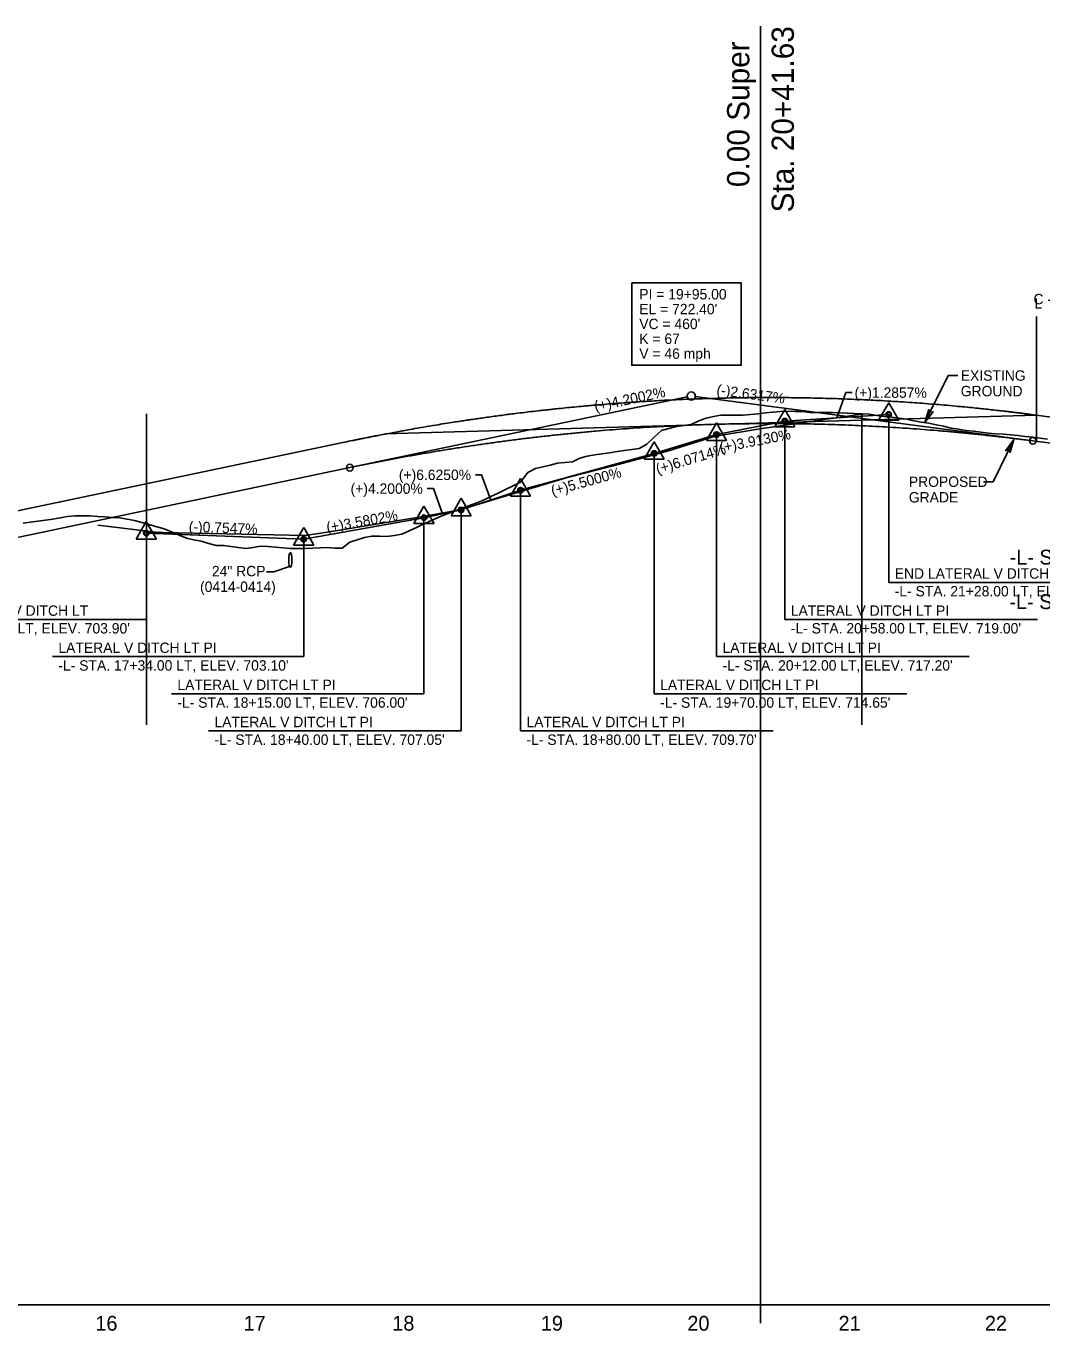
# Model space of a CAD drawing. Extents: x 1518255 to 1527303, y 471773 to 504546.
# Drawn here: x 1520117 to 1520802, y 501127 to 502006 of the extents above; entities that cross this region are included whole.
import ezdxf

# ---------------------------------------------------------------- set-up
doc = ezdxf.new("R2010")
doc.units = 0
for name, color, linetype in [('Exist Profile Cell', 7, 'Continuous'), ('Exist Vertical Profile Ground Line', 7, 'Continuous'), ('Exist Vertical Profile Horizontal Axis Label Major', 7, 'Continuous'), ('Prop Dimension', 7, 'Continuous'), ('Prop Grid Mask', 7, 'Continuous'), ('Prop PFL Cross Pipe CELL', 7, 'Continuous'), ('Prop PFL Cross Pipe Text CELL', 7, 'Continuous'), ('Prop PFL Ditch Label CELL', 7, 'Continuous'), ('Prop Terminator CELL', 7, 'Continuous'), ('Prop Vertical Profile Curve Label', 7, 'Continuous'), ('Prop Vertical Profile Grade', 7, 'Continuous'), ('Prop Vertical Profile Grade Label', 7, 'Continuous'), ('Prop VPI Label', 7, 'Continuous'), ('Scratch_Level_2', 7, 'Continuous'), ('Scratch_Level_3', 7, 'Continuous'), ('Scratch_Level_7', 7, 'Continuous'), ('Scratch_Level_9', 7, 'Continuous')]:
    doc.layers.add(name, color=color, linetype=linetype)

msp = doc.modelspace()

# ---------------------------------------------------------------- linework, layer by layer
at = {"layer": 'Exist Profile Cell'}
msp.add_line((1519570.42, 501145.02), (1521170.42, 501145.02), dxfattribs=at)
at = {"layer": 'Exist Vertical Profile Ground Line'}
for points in [[(1520115.42, 501671.34), (1520120.42, 501672.01), (1520125.42, 501672.69), (1520130.42, 501673.38), (1520135.42, 501674.07), (1520140.42, 501674.84), (1520145.42, 501675.74), (1520150.42, 501676.26), (1520155.42, 501676.35), (1520160.42, 501676.16), (1520165.42, 501675.84), (1520170.42, 501675.53), (1520175.42, 501675.22), (1520180.42, 501674.88), (1520185.42, 501674.02), (1520190.42, 501673.16), (1520195.42, 501671.75), (1520200.42, 501670.34), (1520205.42, 501668.92), (1520210.42, 501667.51), (1520215.42, 501665.45), (1520220.42, 501663.34), (1520225.42, 501661.22), (1520230.42, 501660.13), (1520235.42, 501659.3), (1520240.42, 501657.63), (1520245.42, 501656.2), (1520250.42, 501656.32), (1520255.42, 501655.73), (1520260.42, 501654.98), (1520265.42, 501654.31), (1520270.42, 501655.03), (1520275.42, 501655.83), (1520280.42, 501655.67), (1520285.42, 501655.2), (1520290.42, 501654.73), (1520295.42, 501654.27), (1520300.42, 501654.19), (1520305.42, 501654.36), (1520310.42, 501654.51), (1520315.42, 501654.68), (1520320.42, 501654.96), (1520325.42, 501654.48), (1520330.42, 501654.44), (1520335.42, 501658.63), (1520340.42, 501660.21), (1520345.42, 501661.65), (1520350.42, 501662.58), (1520355.42, 501662.49), (1520360.42, 501662.36), (1520365.42, 501662.98), (1520370.42, 501664.03), (1520375.42, 501666.1), (1520380.42, 501668.5), (1520385.42, 501670.89), (1520390.42, 501673.21), (1520395.42, 501675.39), (1520400.42, 501677.34), (1520405.42, 501679.22), (1520410.42, 501681.11), (1520415.42, 501683), (1520420.42, 501684.89), (1520425.42, 501686.9), (1520430.42, 501689.21), (1520435.42, 501691.57), (1520440.42, 501693.97), (1520445.42, 501696.52), (1520450.42, 501699.04), (1520455.42, 501705.39), (1520460.42, 501708.1), (1520465.42, 501709.26), (1520470.42, 501710.48), (1520475.42, 501711.7), (1520480.42, 501712.22), (1520485.42, 501712.72), (1520490.42, 501715.01), (1520495.42, 501716.42), (1520500.42, 501717.25), (1520505.42, 501718.07), (1520510.42, 501718.79), (1520515.42, 501719.51), (1520520.42, 501720.2), (1520525.42, 501720.9), (1520530.42, 501721.6), (1520535.42, 501724.63), (1520540.42, 501729.18), (1520545.42, 501733.69), (1520550.42, 501734.98), (1520555.42, 501736.34), (1520560.42, 501737.04), (1520565.42, 501737.73), (1520570.42, 501740.35)], [(1520570.42, 501740.35), (1520575.42, 501742.01), (1520580.42, 501743.27), (1520585.42, 501744.04), (1520590.42, 501744.07), (1520595.42, 501744.11), (1520600.42, 501744.14), (1520605.42, 501744.52), (1520610.42, 501745.02), (1520615.42, 501745.53), (1520620.42, 501746), (1520625.42, 501746.44), (1520630.42, 501746.68), (1520635.42, 501746.59), (1520640.42, 501746.45), (1520645.42, 501745.97), (1520650.42, 501745.92), (1520655.42, 501745.86), (1520660.42, 501745.77), (1520665.42, 501745.57), (1520670.42, 501745.37), (1520675.42, 501745.13), (1520680.42, 501744.95), (1520685.42, 501744.79), (1520690.42, 501743.89), (1520695.42, 501743.27), (1520700.42, 501742.7), (1520705.42, 501742.14), (1520710.42, 501741.27), (1520715.42, 501740.26), (1520720.42, 501739.4), (1520725.42, 501738.6), (1520730.42, 501737.62), (1520735.42, 501736.56), (1520740.42, 501735.41), (1520745.42, 501734.57), (1520750.42, 501733.82), (1520755.42, 501733.22), (1520760.42, 501732.61), (1520765.42, 501732.02), (1520770.42, 501731.59), (1520775.42, 501731.16), (1520780.42, 501730.74), (1520785.42, 501730.3), (1520790.42, 501729.78), (1520795.42, 501729.18), (1520800.42, 501728.53), (1520805.42, 501727.89)]]:
    msp.add_lwpolyline(points, dxfattribs=at)
at = {"layer": 'Prop Dimension'}
for p, q in [((1520738.55, 501770.75), (1520722.8, 501739.02)), ((1520744.94, 501770.75), (1520738.55, 501770.75)), ((1520768.65, 501699.24), (1520782.71, 501727.57)), ((1520762.26, 501699.24), (1520768.65, 501699.24))]:
    msp.add_line(p, q, dxfattribs=at)
at = {"layer": 'Prop Grid Mask'}
msp.add_lwpolyline([(1520525.4, 501833.18), (1520598.93, 501833.18), (1520598.93, 501777.64), (1520525.4, 501777.64)], close=True, dxfattribs=at)
at = {"layer": 'Prop PFL Cross Pipe CELL'}
msp.add_ellipse((1520295.42, 501646.47), major_axis=(0, -5), ratio=0.2, dxfattribs=at)
at = {"layer": 'Prop PFL Cross Pipe Text CELL'}
for p, q in [((1520279.32, 501638.53), (1520284.25, 501638.53)), ((1520284.25, 501638.53), (1520294.91, 501642.16))]:
    msp.add_line(p, q, dxfattribs=at)
at = {"layer": 'Prop PFL Ditch Label CELL'}
for p, q in [((1520663.42, 501742.27), (1520669.61, 501759.26)), ((1520669.61, 501759.26), (1520673.7, 501759.26)), ((1520698.41, 501752.37), (1520691.64, 501740.61)), ((1520698.41, 501752.37), (1520705.23, 501740.61)), ((1520582.42, 501731.02), (1520628.42, 501740.02)), ((1520628.41, 501747.87), (1520621.64, 501736.11)), ((1520628.41, 501747.87), (1520635.23, 501736.11)), ((1520628.42, 501740.02), (1520698.42, 501744.52)), ((1520628.42, 501740.02), (1520628.42, 501606.48)), ((1520691.64, 501740.61), (1520705.23, 501740.61)), ((1520698.42, 501744.52), (1520698.42, 501631.48)), ((1520540.42, 501718.27), (1520582.42, 501731.02)), ((1520582.41, 501738.87), (1520575.64, 501727.11)), ((1520582.41, 501738.87), (1520589.23, 501727.11)), ((1520582.42, 501731.02), (1520582.42, 501581.48)), ((1520621.64, 501736.11), (1520635.23, 501736.11)), ((1520540.41, 501726.12), (1520533.64, 501714.36)), ((1520540.41, 501726.12), (1520547.23, 501714.36)), ((1520575.64, 501727.11), (1520589.23, 501727.11)), ((1520450.42, 501693.52), (1520540.42, 501718.27)), ((1520533.64, 501714.36), (1520547.23, 501714.36)), ((1520540.42, 501718.27), (1520540.42, 501556.48)), ((1520424.22, 501703.88), (1520420.13, 501703.88)), ((1520430.42, 501686.89), (1520424.22, 501703.88)), ((1520450.41, 501701.37), (1520443.64, 501689.61)), ((1520450.41, 501701.37), (1520457.23, 501689.61)), ((1520391.72, 501694.63), (1520387.63, 501694.63)), ((1520397.92, 501677.64), (1520391.72, 501694.63)), ((1520410.41, 501688.12), (1520403.64, 501676.36)), ((1520410.41, 501688.12), (1520417.23, 501676.36)), ((1520410.42, 501680.27), (1520450.42, 501693.52)), ((1520443.64, 501689.61), (1520457.23, 501689.61)), ((1520450.42, 501693.52), (1520450.42, 501531.48)), ((1520385.41, 501682.87), (1520378.64, 501671.11)), ((1520385.41, 501682.87), (1520392.23, 501671.11)), ((1520385.42, 501675.02), (1520410.42, 501680.27)), ((1520410.42, 501680.27), (1520410.42, 501531.48)), ((1520198.41, 501672.37), (1520191.64, 501660.61)), ((1520198.41, 501672.37), (1520205.23, 501660.61)), ((1520304.42, 501660.52), (1520385.42, 501675.02)), ((1520378.64, 501671.11), (1520392.23, 501671.11)), ((1520385.42, 501675.02), (1520385.42, 501556.48)), ((1520403.64, 501676.36), (1520417.23, 501676.36)), ((1520191.64, 501660.61), (1520205.23, 501660.61)), ((1520198.42, 501664.52), (1520304.42, 501660.52)), ((1520198.42, 501664.52), (1520198.42, 501606.48)), ((1520304.41, 501668.37), (1520297.64, 501656.61)), ((1520304.41, 501668.37), (1520311.23, 501656.61)), ((1520304.42, 501660.52), (1520304.42, 501581.48)), ((1520297.64, 501656.61), (1520311.23, 501656.61)), ((1520698.42, 501631.48), (1520868.57, 501631.48)), ((1520028.27, 501606.48), (1520198.42, 501606.48)), ((1520628.42, 501606.48), (1520798.57, 501606.48)), ((1520135.13, 501581.48), (1520304.42, 501581.48)), ((1520582.42, 501581.48), (1520752.57, 501581.48)), ((1520215.27, 501556.48), (1520385.42, 501556.48)), ((1520540.42, 501556.48), (1520710.57, 501556.48)), ((1520240.27, 501531.48), (1520410.42, 501531.48)), ((1520450.42, 501531.48), (1520620.57, 501531.48))]:
    msp.add_line(p, q, dxfattribs=at)
for centre, radius in [((1520628.42, 501740.02), 1.84), ((1520628.42, 501740.02), 1.26), ((1520698.42, 501744.52), 1.84), ((1520698.42, 501744.52), 1.26), ((1520582.42, 501731.02), 1.84), ((1520582.42, 501731.02), 1.26), ((1520540.42, 501718.27), 1.84), ((1520540.42, 501718.27), 1.26), ((1520450.42, 501693.52), 1.84), ((1520450.42, 501693.52), 1.26), ((1520410.42, 501680.27), 1.84), ((1520410.42, 501680.27), 1.26), ((1520385.42, 501675.02), 1.84), ((1520385.42, 501675.02), 1.26), ((1520198.42, 501664.52), 1.84), ((1520198.42, 501664.52), 1.26), ((1520304.42, 501660.52), 1.84), ((1520304.42, 501660.52), 1.26)]:
    msp.add_circle(centre, radius, dxfattribs=at)
at = {"layer": 'Prop Terminator CELL'}
for points in [[(1520725.41, 501747.77), (1520722.8, 501739.02), (1520728.25, 501746.41), (1520726.31, 501746.1)], [(1520780.1, 501718.82), (1520782.71, 501727.57), (1520777.26, 501720.18), (1520779.2, 501720.5)]]:
    msp.add_lwpolyline(points, close=True, dxfattribs=at)
at = {"layer": 'Prop Vertical Profile Curve Label'}
msp.add_line((1520797.9, 501726.42), (1520797.9, 501810.55), dxfattribs=at)
for centre in [(1520795.42, 501726.75), (1520335.42, 501708.71)]:
    msp.add_circle(centre, 2.25, dxfattribs=at)
at = {"layer": 'Prop Vertical Profile Grade'}
for p, q in [((1520795.42, 501726.75), (1520830.42, 501722.14)), ((1519930.42, 501623.66), (1520335.42, 501708.71))]:
    msp.add_line(p, q, dxfattribs=at)
msp.add_spline([(1520335.42, 501708.71), (1520344.62, 501710.61), (1520353.82, 501712.45), (1520363.02, 501714.23), (1520372.22, 501715.94), (1520381.42, 501717.59), (1520390.62, 501719.17), (1520399.82, 501720.7), (1520409.02, 501722.16), (1520418.22, 501723.56), (1520427.42, 501724.89), (1520436.62, 501726.16), (1520445.82, 501727.37), (1520455.02, 501728.52), (1520464.22, 501729.6), (1520473.42, 501730.62), (1520482.62, 501731.58), (1520491.82, 501732.48), (1520501.02, 501733.31), (1520510.22, 501734.08), (1520519.42, 501734.78), (1520528.62, 501735.43), (1520537.82, 501736.01), (1520547.02, 501736.53), (1520556.22, 501736.98), (1520565.42, 501737.37), (1520574.62, 501737.7), (1520583.82, 501737.97), (1520593.02, 501738.17), (1520602.22, 501738.31), (1520611.42, 501738.39), (1520620.62, 501738.41), (1520629.82, 501738.36), (1520639.02, 501738.25), (1520648.22, 501738.07), (1520657.42, 501737.84), (1520666.62, 501737.54), (1520675.82, 501737.18), (1520685.02, 501736.75), (1520694.22, 501736.26), (1520703.42, 501735.71), (1520712.62, 501735.1), (1520721.82, 501734.42), (1520731.02, 501733.68), (1520740.22, 501732.88), (1520749.42, 501732.02), (1520758.62, 501731.09), (1520767.82, 501730.1), (1520777.02, 501729.05), (1520786.22, 501727.93), (1520795.42, 501726.75)], degree=3, dxfattribs=at)
at = {"layer": 'Prop VPI Label'}
for p, q in [((1520335.42, 501708.71), (1520562.72, 501756.45)), ((1520795.42, 501726.75), (1520568.14, 501756.66))]:
    msp.add_line(p, q, dxfattribs=at)
msp.add_circle((1520565.42, 501757.02), 2.75, dxfattribs=at)
at = {"layer": 'Scratch_Level_3'}
for p, q in [((1520198.42, 501745.02), (1520198.42, 501535.6)), ((1520613.26, 501735.02), (1520647.31, 501740.02)), ((1520647.31, 501740.02), (1520681.54, 501745.02)), ((1520680.42, 501745.02), (1520680.42, 501535.6)), ((1520581.57, 501730.02), (1520613.26, 501735.02)), ((1520550, 501720.02), (1520565.74, 501725.02)), ((1520565.74, 501725.02), (1520581.57, 501730.02)), ((1520512.83, 501710.02), (1520532.14, 501715.02)), ((1520532.14, 501715.02), (1520550, 501720.02)), ((1520474.16, 501700.02), (1520493.44, 501705.02)), ((1520493.44, 501705.02), (1520512.83, 501710.02)), ((1520408.71, 501680.02), (1520480.42, 501701.69)), ((1520456.05, 501695.02), (1520474.16, 501700.02)), ((1520425.25, 501685.02), (1520440.62, 501690.02)), ((1520440.62, 501690.02), (1520456.05, 501695.02)), ((1520379.38, 501675.02), (1520408.71, 501680.02)), ((1520165.79, 501670.02), (1520206.79, 501665.02)), ((1520318.83, 501665.02), (1520349.06, 501670.02)), ((1520349.06, 501670.02), (1520379.38, 501675.02)), ((1520198.42, 501665.19), (1520305.28, 501662.92)), ((1520305.28, 501662.92), (1520318.83, 501665.02))]:
    msp.add_line(p, q, dxfattribs=at)
at = {"layer": 'Scratch_Level_7'}
for p, q in [((1520797.9, 501744.07), (1520359.12, 501731.57)), ((1520797.7, 501744.1), (1520832.7, 501739.5)), ((1520797.9, 501726.03), (1520797.9, 501743.63)), ((1519751.82, 501604.03), (1520331.82, 501725.84))]:
    msp.add_line(p, q, dxfattribs=at)
msp.add_open_spline([(1520331.87, 501725.85), (1520334.23, 501726.34), (1520337.18, 501726.95), (1520340.21, 501727.57), (1520340.91, 501727.72), (1520341.02, 501727.74), (1520341.06, 501727.75), (1520341.07, 501727.75), (1520341.09, 501727.76), (1520341.12, 501727.76), (1520341.3, 501727.8), (1520341.78, 501727.9), (1520342.24, 501727.99), (1520343.76, 501728.3), (1520344.97, 501728.54), (1520347.37, 501729.02), (1520348.56, 501729.25), (1520349.9, 501729.52), (1520350.12, 501729.56), (1520350.35, 501729.61), (1520350.43, 501729.62), (1520350.45, 501729.63), (1520350.46, 501729.63), (1520350.49, 501729.63), (1520350.55, 501729.64), (1520350.9, 501729.71), (1520351.84, 501729.9), (1520355.13, 501730.54), (1520360.52, 501731.57), (1520365.31, 501732.46), (1520370.11, 501733.35), (1520372.51, 501733.78), (1520379.71, 501735.07), (1520384.52, 501735.9), (1520394.14, 501737.51), (1520398.96, 501738.29), (1520406.19, 501739.43), (1520408.6, 501739.8), (1520413.42, 501740.54), (1520415.84, 501740.9), (1520420.66, 501741.6), (1520423.08, 501741.95), (1520427.91, 501742.64), (1520432.74, 501743.31), (1520437.58, 501743.95), (1520442.42, 501744.58), (1520444.84, 501744.89), (1520452.1, 501745.8), (1520456.95, 501746.38), (1520464.22, 501747.22), (1520466.64, 501747.49), (1520471.49, 501748.02), (1520473.92, 501748.28), (1520481.2, 501749.04), (1520486.06, 501749.52), (1520493.35, 501750.2), (1520495.78, 501750.42), (1520500.64, 501750.84), (1520503.07, 501751.05), (1520510.37, 501751.65), (1520515.23, 501752.03), (1520524.97, 501752.73), (1520529.84, 501753.05), (1520539.58, 501753.65), (1520544.45, 501753.92), (1520554.2, 501754.42), (1520559.08, 501754.64), (1520568.83, 501755.02), (1520573.71, 501755.19), (1520583.47, 501755.48), (1520588.35, 501755.59), (1520598.11, 501755.77), (1520602.99, 501755.83), (1520612.75, 501755.91), (1520617.63, 501755.92), (1520632.28, 501755.87), (1520642.04, 501755.74), (1520661.56, 501755.26), (1520671.31, 501754.91), (1520685.94, 501754.24), (1520690.82, 501753.99), (1520700.56, 501753.43), (1520705.43, 501753.13), (1520715.17, 501752.47), (1520720.04, 501752.12), (1520729.77, 501751.36), (1520734.63, 501750.95), (1520744.36, 501750.09), (1520749.22, 501749.63), (1520756.5, 501748.9), (1520758.93, 501748.65), (1520763.78, 501748.14), (1520768.63, 501747.62), (1520774.09, 501747.01), (1520777.42, 501746.62), (1520778.41, 501746.5), (1520778.82, 501746.45), (1520778.94, 501746.44), (1520779.01, 501746.43), (1520779.05, 501746.43), (1520779.24, 501746.41), (1520779.39, 501746.39), (1520780.73, 501746.23), (1520781.94, 501746.09), (1520784.37, 501745.79), (1520785.6, 501745.65), (1520787.14, 501745.45), (1520787.45, 501745.41), (1520787.91, 501745.35), (1520788.11, 501745.33), (1520788.32, 501745.3), (1520788.39, 501745.29), (1520788.42, 501745.29), (1520788.43, 501745.29), (1520788.44, 501745.29), (1520788.44, 501745.29), (1520788.45, 501745.29), (1520788.53, 501745.28), (1520789.2, 501745.19), (1520792.26, 501744.8), (1520795.25, 501744.41), (1520797.64, 501744.11)], degree=3, dxfattribs=at)
at = {"layer": 'Scratch_Level_9'}
msp.add_line((1520612.05, 501132.52), (1520612.05, 502006.08), dxfattribs=at)

# ---------------------------------------------------------------- texts
at = {"layer": 'Exist Vertical Profile Horizontal Axis Label Major'}
for s, p in [('16', (1520164.1, 501127.52)), ('17', (1520263.95, 501127.52)), ('18', (1520364.08, 501127.52)), ('19', (1520464.12, 501127.52)), ('20', (1520562.8, 501127.52)), ('21', (1520664.64, 501127.52)), ('22', (1520763.19, 501127.52))]:
    msp.add_text(s, height=10, dxfattribs=at).set_placement(p)
at = {"layer": 'Prop Dimension'}
for s, p in [('EXISTING', (1520746.94, 501767.26)), ('GROUND', (1520746.94, 501756.76)), ('PROPOSED', (1520711.96, 501695.75)), ('GRADE', (1520711.96, 501685.25))]:
    msp.add_text(s, height=7, dxfattribs=at).set_placement(p)
at = {"layer": 'Prop PFL Cross Pipe Text CELL'}
for s, p in [('24" RCP', (1520242.58, 501635.55)), ('(0414-0414)', (1520234.59, 501625.05))]:
    msp.add_text(s, height=7, dxfattribs=at).set_placement(p)
at = {"layer": 'Prop PFL Ditch Label CELL'}
for s, p in [('(+)1.2857%', (1520675.42, 501755.76)), ('(+)6.6250%', (1520368.47, 501700.38)), ('(+)4.2000%', (1520335.97, 501691.13)), ('END LATERAL V DITCH LT', (1520702.47, 501633.93)), ("-L- STA. 21+28.00 LT, ELEV. 719.90'", (1520702.47, 501622.03)), ('BEGIN LATERAL V DITCH LT', (1520032.32, 501608.93)), ('LATERAL V DITCH LT PI', (1520632.47, 501608.93)), ("-L- STA. 16+28.00 LT, ELEV. 703.90'", (1520032.32, 501597.03)), ("-L- STA. 20+58.00 LT, ELEV. 719.00'", (1520632.47, 501597.03)), ('LATERAL V DITCH LT PI', (1520139.18, 501583.93)), ('LATERAL V DITCH LT PI', (1520586.47, 501583.93)), ("-L- STA. 17+34.00 LT, ELEV. 703.10'", (1520139.18, 501572.03)), ("-L- STA. 20+12.00 LT, ELEV. 717.20'", (1520586.47, 501572.03)), ('LATERAL V DITCH LT PI', (1520219.32, 501558.93)), ('LATERAL V DITCH LT PI', (1520544.47, 501558.93)), ("-L- STA. 18+15.00 LT, ELEV. 706.00'", (1520219.32, 501547.03)), ("-L- STA. 19+70.00 LT, ELEV. 714.65'", (1520544.47, 501547.03)), ('LATERAL V DITCH LT PI', (1520244.32, 501533.93)), ('LATERAL V DITCH LT PI', (1520454.47, 501533.93)), ("-L- STA. 18+40.00 LT, ELEV. 707.05'", (1520244.32, 501522.03)), ("-L- STA. 18+80.00 LT, ELEV. 709.70'", (1520454.47, 501522.03))]:
    msp.add_text(s, height=7, dxfattribs=at).set_placement(p)
for s, rotation, p in [('(+)3.9130%', 11.0702, (1520585.18, 501718.7)), ('(+)6.0714%', 16.88679, (1520542.85, 501704.27)), ('(+)5.5000%', 15.37625, (1520472.06, 501689.62)), ('(+)3.5802%', 10.14915, (1520320.36, 501664.93)), ('(-)0.7547%', 357.83892, (1520226.89, 501665.62))]:
    msp.add_text(s, height=7, rotation=rotation, dxfattribs=at).set_placement(p)
at = {"layer": 'Prop Vertical Profile Curve Label'}
for s, p in [('C -Y2-', (1520795.92, 501818.71)), ('L', (1520796.58, 501815.84)), ("VC = 460'", (1520530.42, 501802.02)), ('K = 67', (1520530.42, 501792.01)), ('V = 46 mph', (1520530.42, 501782.02))]:
    msp.add_text(s, height=7, dxfattribs=at).set_placement(p)
at = {"layer": 'Prop Vertical Profile Grade Label'}
for s, rotation, p in [('(+)4.2002%', 11.86025, (1520500.9, 501746.53)), ('(-)2.6317%', 352.50367, (1520582.14, 501757.84))]:
    msp.add_text(s, height=7, rotation=rotation, dxfattribs=at).set_placement(p)
at = {"layer": 'Prop VPI Label'}
for s, p in [('PI = 19+95.00', (1520530.42, 501822.02)), ("EL = 722.40'", (1520530.42, 501812.02))]:
    msp.add_text(s, height=7, dxfattribs=at).set_placement(p)
at = {"layer": 'Scratch_Level_2'}
for s, p in [('-L- Sta. 23+68.39 = TOR_LT Sta. 10+52.56', (1520779.86, 501643.46)), ('-L- Sta. 23+73.04 = TOR_RT Sta. 10+52.48', (1520779.7, 501613.46))]:
    msp.add_text(s, height=10, rotation=360, dxfattribs=at).set_placement(p)
at = {"layer": 'Scratch_Level_9'}
for s, p in [('Sta. 20+41.63', (1520634.55, 501880.55)), ('0.00 Super', (1520604.55, 501897.66))]:
    msp.add_text(s, height=15, rotation=90, dxfattribs=at).set_placement(p)

doc.saveas('drawing.dxf')
